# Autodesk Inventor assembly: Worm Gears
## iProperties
Created: 2008-01
Part Number: Worm Gears
Document SubType Name: Assembly
Designer: eruiz-tagle
Mass: 6.17747 g
Surface Area: 13.4788 cm^2
Volume: 0.785938 cm^3
Density: 7.86 g/cm^3
ClientObjectVersion: 1
Author: eruiz-tagle
